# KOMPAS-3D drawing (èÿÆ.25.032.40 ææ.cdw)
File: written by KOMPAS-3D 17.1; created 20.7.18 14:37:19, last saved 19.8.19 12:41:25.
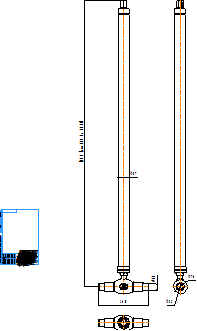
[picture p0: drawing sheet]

Sheet 1: A4, portrait

Title block, sheet 1: name: КШТ.25.032.40 С/С; sheets: 1; sheet format: A4; stored path: C:\Users\kka\KOMPAS_Work\Модели кранов для исследований\DN40\С удлинением\КШТ.22.040.40 СС.cdw

Views: Вид 1, Проекционный вид 2, Проекционный вид 3
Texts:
  kka
  adl
  (от 245 до 5000)
  Рама для чертежей
  Лит-Масса-Масштаб
  Материал-Предприятие
  Масштаб
  Изм.
  Лист
  № докум.
  Подп.
  Дата
  Лит.
  Разраб.
  Пров.
  Т.контр.
  Листов
  Внимание! Данный продукт является объектом авторского права ООО «Торговый Дом АДЛ».
  Запрещается изменение, копирование, распространение
  (в том числе путем копирования на другие сайты и ресурсы в Интернете)
  или любое иное использование информации и объектов без предварительного
  согласия правообладателя (ООО «Торговый Дом АДЛ»).
  Н.контр.
  Утв.
  ООО "Торговый дом АДЛ"
  Изменение
  Номер документа
  Подпись
  Обозначение документа
  Наименование изделия
  Масса изделия по ГОСТ 2.109-73
  Порядковый номер листа
  Общее количество листов в документе
  Характер работы, выполненной лицом, подписавшим документ
  Наименование или индекс предприятия, выпускающего документ
  Инв. № подл.
  Подп. и дата
  Взам. инв. №
  Инв. № дубл.
  Инвентарный номер подлинника по ГОСТ 2.501-68
  Подпись принявшего подлинник в отдел технической документации
  Инвентарный номер подлинника, взамен которого выпущен данный подлинник
  Инвентарный номер дубликата по ГОСТ 2.502-68
  Подпись принявшего дубликат в отдел технической документации
  Справ. №
  Перв. примен.
  Обозначение документа, взамен или на основании которого выпущен данный документ
  Обозначение документа, в котором впервые записан данный документ
  Подпись лица, копировавшего чертеж
  Обозначение формата листа
  !Рама для чертежа
Dimensions and other numbers on the sheet: 260; 1500; 38; 57; 76; 32; 1:1; 1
